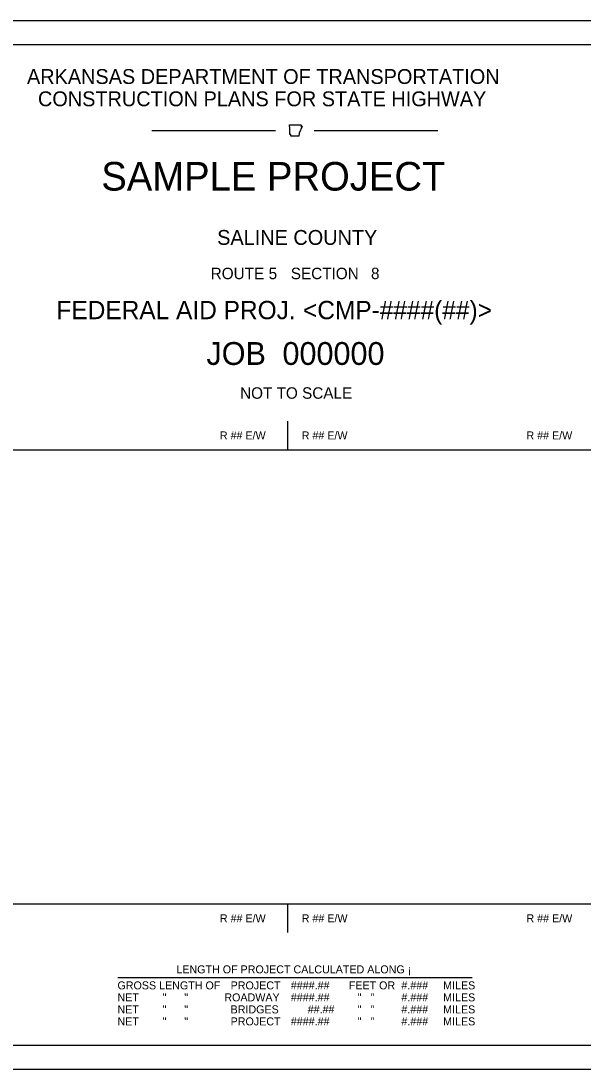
# Model space of a CAD drawing. Extents: x -0.25 to 1.42, y 0 to 0.92.
# Drawn here: x 0.469 to 0.96, y 0 to 0.917 of the extents above; entities that cross this region are included whole.
import ezdxf

# ---------------------------------------------------------------- set-up
doc = ezdxf.new("R2010")
doc.units = 0
for name, color, linetype in [('DSN_DRFT_DNC', 7, 'Continuous'), ('SHET_Annotations', 7, 'Continuous'), ('SHET_Border-Lines', 7, 'Continuous'), ('SHET_Border-Text', 7, 'Continuous')]:
    doc.layers.add(name, color=color, linetype=linetype)

msp = doc.modelspace()

# ---------------------------------------------------------------- linework, layer by layer
at = {"layer": 'DSN_DRFT_DNC'}
msp.add_lwpolyline([(0.38477, 0.54167), (1.0319, 0.54167), (1.0319, 0.1443), (0.38477, 0.1443)], close=True, dxfattribs=at)
at = {"layer": 'SHET_Annotations'}
for p, q in [((0.70182, 0.56667), (0.70183, 0.54167)), ((0.70182, 0.1443), (0.70183, 0.1193))]:
    msp.add_line(p, q, dxfattribs=at)
at = {"layer": 'SHET_Border-Lines'}
for points in [[(0, 0), (1.41667, 0), (1.41667, 0.91667), (0, 0.91667)], [(0.02083, 0.02083), (1.39583, 0.02083), (1.39583, 0.89583), (0.02083, 0.89583)]]:
    msp.add_lwpolyline(points, close=True, dxfattribs=at)
at = {"layer": 'SHET_Border-Text'}
for p, q in [((0.58333, 0.82083), (0.69135, 0.82083)), ((0.72532, 0.82083), (0.83333, 0.82083)), ((0.55333, 0.08017), (0.86333, 0.08017))]:
    msp.add_line(p, q, dxfattribs=at)
msp.add_lwpolyline([(0.70492, 0.81582), (0.70492, 0.81733), (0.70387, 0.81745), (0.70406, 0.82268), (0.70367, 0.82577), (0.71388, 0.82585), (0.71403, 0.82521), (0.71343, 0.8244), (0.71485, 0.82447), (0.71216, 0.81856), (0.71174, 0.81581)], close=True, dxfattribs=at)

# ---------------------------------------------------------------- texts
at = {"layer": 'SHET_Annotations'}
for s, height, p in [('SAMPLE PROJECT', 0.025, (0.53902, 0.76833)), ('SALINE COUNTY', 0.013, (0.64036, 0.72083)), ('ROUTE ', 0.01, (0.6347, 0.69083)), ('5', 0.01, (0.6854, 0.69083)), ('   SECTION ', 0.01, (0.69361, 0.69083)), ('8', 0.01, (0.77492, 0.69083)), ('FEDERAL AID PROJ. ', 0.016, (0.49978, 0.65583)), ('<CMP-####(##)>', 0.016, (0.71543, 0.65583)), ('JOB ', 0.02, (0.63097, 0.61583)), ('000000', 0.02, (0.69748, 0.61583)), ('R ## E/W', 0.007, (0.64273, 0.55067)), ('R ## E/W', 0.007, (0.71433, 0.55067)), ('R ## E/W', 0.007, (0.9109, 0.55067)), ('R ## E/W', 0.007, (0.64273, 0.1283)), ('R ## E/W', 0.007, (0.71433, 0.1283)), ('R ## E/W', 0.007, (0.9109, 0.1283)), ('####.##', 0.007, (0.70479, 0.06967)), ('#.### ', 0.007, (0.80148, 0.06967)), ('MILES', 0.007, (0.83801, 0.06967)), ('####.##', 0.007, (0.70479, 0.05917)), ('#.### ', 0.007, (0.80148, 0.05917)), ('MILES', 0.007, (0.83801, 0.05917)), ('##.##', 0.007, (0.71952, 0.04867)), ('#.### ', 0.007, (0.80148, 0.04867)), ('MILES', 0.007, (0.83801, 0.04867)), ('####.##', 0.007, (0.70479, 0.03817)), ('#.### ', 0.007, (0.80148, 0.03817)), ('MILES', 0.007, (0.83801, 0.03817))]:
    msp.add_text(s, height=height, dxfattribs=at).set_placement(p)
at = {"layer": 'SHET_Border-Text'}
for s, height, p in [('ARKANSAS DEPARTMENT OF TRANSPORTATION', 0.013, (0.474, 0.86158)), ('CONSTRUCTION PLANS FOR STATE HIGHWAY', 0.013, (0.48363, 0.84208)), ('NOT TO SCALE', 0.01, (0.6604, 0.58625)), ('LENGTH OF PROJECT CALCULATED ALONG ¡', 0.007, (0.60467, 0.08367)), ('GROSS LENGTH OF', 0.007, (0.55315, 0.06967)), ('PROJECT', 0.007, (0.65213, 0.06967)), ('FEET OR', 0.007, (0.75548, 0.06967)), ('NET        "      "', 0.007, (0.55315, 0.05917)), ('ROADWAY', 0.007, (0.64666, 0.05917)), ('   "   "', 0.007, (0.75548, 0.05917)), ('NET        "      "', 0.007, (0.55315, 0.04867)), ('BRIDGES', 0.007, (0.65209, 0.04867)), ('   "   "', 0.007, (0.75548, 0.04867)), ('NET        "      "', 0.007, (0.55315, 0.03817)), ('PROJECT', 0.007, (0.65213, 0.03817)), ('   "   "', 0.007, (0.75548, 0.03817))]:
    msp.add_text(s, height=height, dxfattribs=at).set_placement(p)

doc.saveas('drawing.dxf')
